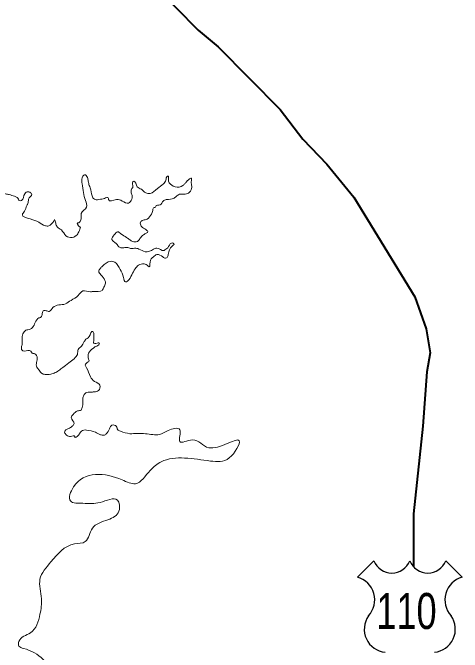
# Model space of a CAD drawing. Extents: x 553962 to 842807, y 8883888 to 9032388.
# Drawn here: x 579563 to 583934, y 8979171 to 8985392 of the extents above; entities that cross this region are included whole.
import ezdxf
from ezdxf.enums import TextEntityAlignment as Align

# ---------------------------------------------------------------- set-up
doc = ezdxf.new("R2010")
doc.units = 0
doc.header["$LTSCALE"] = 200
for name, color, linetype, lineweight in [('12', 7, 'Continuous', 25), ('25', 7, 'Continuous', 13), ('48', 7, 'Continuous', 25)]:
    doc.layers.add(name, color=color, linetype=linetype, lineweight=lineweight)

msp = doc.modelspace()

# ---------------------------------------------------------------- linework, layer by layer
at = {"layer": '12', "lineweight": 40}
msp.add_lwpolyline([(577759.9, 8988875.8), (577832.5, 8988674.7), (577901.5, 8988571.1), (578184.7, 8988310.3), (578513.4, 8987946.2), (578671.2, 8987814.3), (579419.2, 8987100.9), (579808.1, 8986794.1), (580283, 8986357.3), (580496.3, 8986108), (581364.8, 8985224.5), (581561.3, 8985062.5), (582162.5, 8984452.7), (582384.7, 8984161.9), (582616.4, 8983918.8), (582880.2, 8983596.7), (583472.4, 8982628.4), (583582.5, 8982317.7), (583621.7, 8982083.2), (583591.6, 8981897.8), (583552.5, 8981370), (583461.7, 8980518.1), (583461.7, 8980001.2)], dxfattribs=at)
at = {"layer": '25'}
for points in [[(579970.3, 8983381.7), (579928.3, 8983326.2), (579913.3, 8983318.6), (579880.6, 8983319.8), (579816, 8983353.5), (579732.6, 8983386), (579656.6, 8983427.2), (579677.5, 8983461.2), (579700.7, 8983516.6), (579706.8, 8983528), (579715.1, 8983564.5), (579723.5, 8983590.9), (579747, 8983622.4), (579727.8, 8983646.2), (579713.9, 8983650), (579679, 8983632.2), (579647.2, 8983565.5), (579623.3, 8983566.7), (579619.4, 8983578), (579581.3, 8983606.8), (579528.2, 8983623), (579513.1, 8983626.7), (579471.5, 8983636.7), (579433.4, 8983665.5), (579440.4, 8983701.9), (579442.4, 8983737.2), (579441.2, 8983739.7), (579447, 8983768.6), (579413, 8983867.8), (579391.3, 8983892.9), (579318.5, 8983971.9), (579294.2, 8984005.8), (579301.2, 8984042.2), (579315.8, 8984077.5), (579343, 8984115.3), (579355.3, 8984132.9), (579360.2, 8984143)], [(580290.3, 8983788.7), (580262.3, 8983816.3), (580235.2, 8983772.2), (580237.1, 8983729.5), (580249.6, 8983642.7), (580269.5, 8983564.8), (580280.4, 8983502), (580228.5, 8983437.7), (580228.9, 8983411.3), (580225.6, 8983377.4), (580205.8, 8983349.7), (580190.8, 8983343.3), (580198.6, 8983327), (580199.9, 8983323.2), (580212.7, 8983309.5), (580216.4, 8983308.2), (580211.9, 8983275.5), (580188.6, 8983232.7), (580142.4, 8983206.2), (580080.6, 8983222.3), (580035.8, 8983278.8), (579995.2, 8983308.8), (579980.9, 8983344), (579975.5, 8983366.6), (579970.3, 8983381.7)], [(581134, 8983136.2), (581123.8, 8983150.6), (581105.6, 8983150.6), (581070.3, 8983105.8), (581052.9, 8983091.9), (581034.2, 8983079.3), (580963.5, 8983103), (580932.2, 8983091.6), (580892.3, 8983071.3), (580850.8, 8983067.4), (580790.1, 8983093.7), (580748.6, 8983101.1), (580717.2, 8983098.5), (580683.1, 8983107.2), (580642.9, 8983105.8), (580622.8, 8983104.5), (580595, 8983115.7), (580573.2, 8983143.3), (580544, 8983165.8), (580526.1, 8983187.2), (580550.7, 8983231.2), (580582.9, 8983261.5), (580614.6, 8983241.5), (580670.4, 8983206.5), (580700.9, 8983182.7), (580728.8, 8983167.7), (580775.3, 8983167.8), (580800.1, 8983195.5), (580833.5, 8983232.1), (580860.9, 8983248.5), (580877.1, 8983263.7), (580868.1, 8983274.9), (580826.2, 8983303.7), (580804.4, 8983335.1), (580804.2, 8983354), (580830.3, 8983372.9), (580870.4, 8983385.6), (580911.2, 8983432.2), (580924.6, 8983468.7), (580931.7, 8983493.9), (580954.2, 8983506.5), (580954.2, 8983507.8), (580996.7, 8983524.3), (581025.1, 8983560.8), (581056.3, 8983574.7), (581131.6, 8983588.8), (581158.9, 8983611.5), (581195.2, 8983628), (581227.9, 8983628), (581273, 8983638.2), (581301.3, 8983683.6), (581303.5, 8983703.7), (581299.1, 8983749), (581299.9, 8983784.2), (581260.8, 8983756), (581236.5, 8983729.9), (581217.9, 8983712.2), (581141.4, 8983698.2), (581085.5, 8983738.3), (581076.3, 8983772.2), (581072.1, 8983803.6), (581068.3, 8983802.3), (581051.3, 8983763.3), (581027.9, 8983726.8), (580969.4, 8983681.3), (580898.4, 8983634.6), (580856.8, 8983640.8), (580813.6, 8983674.6), (580774.3, 8983699.6), (580739.6, 8983752.3), (580732.1, 8983748.5), (580731.6, 8983699.5), (580718.1, 8983675.6), (580716, 8983641.6), (580725.3, 8983605.2), (580720.6, 8983578.8), (580689.7, 8983539.7), (580627.8, 8983560.9), (580572.3, 8983574.6), (580493.2, 8983574.3), (580490.4, 8983591.9), (580477.8, 8983595.6), (580476.5, 8983595.6), (580454, 8983585.5), (580401.3, 8983576.6), (580373.7, 8983572.7), (580343.3, 8983592.7), (580322.1, 8983669.4), (580307.7, 8983710.8), (580297.1, 8983754.8), (580290.3, 8983788.7)], [(579888.2, 8982493.8), (579915.9, 8982486.3), (579954.3, 8982525.4), (580074.6, 8982559.7), (580129.7, 8982594), (580199.2, 8982640.5), (580243.8, 8982685.9), (580319.4, 8982677.4), (580352, 8982681.2), (580431.1, 8982691.5), (580449.5, 8982723), (580464.1, 8982760.8), (580459.9, 8982787.2), (580418.9, 8982842.4), (580399.6, 8982877.5), (580413.1, 8982902.7), (580435.4, 8982927.9), (580511.4, 8982973.4), (580556.8, 8982964.7), (580606.8, 8982894.5), (580640.6, 8982816.6), (580660, 8982773.9), (580678.8, 8982781.5), (580720.7, 8982842), (580753.8, 8982901.2), (580786, 8982936.5), (580839.9, 8982949.2), (580880.4, 8982928), (580889.3, 8982920.5), (580898.7, 8982967), (580930.7, 8983017.4), (580964.4, 8983038.9), (581023.8, 8983016.4), (581049.1, 8983003.9), (581064.1, 8983011.5), (581075, 8983041.7), (581112.8, 8983122.3), (581134, 8983136.2)], [(580701.6, 8981295.5), (580609.5, 8981320.4), (580584.1, 8981335.4), (580569.8, 8981369.3), (580528.2, 8981380.5), (580503.6, 8981343.9), (580472.8, 8981294.8), (580447.8, 8981282.2), (580415.1, 8981287.1), (580367, 8981310.8), (580278.7, 8981332), (580253.6, 8981331.9), (580216.2, 8981301.6), (580199, 8981278.9), (580166.5, 8981262.5), (580166.4, 8981268.8), (580124.9, 8981269.9), (580087, 8981282.4), (580067.8, 8981308.7), (580071.3, 8981326.3), (580116.2, 8981351.6), (580143.6, 8981371.8), (580160.9, 8981394.5), (580132.5, 8981452.2), (580152.1, 8981485), (580191.9, 8981517.8), (580212, 8981521.6), (580220.8, 8981522.9), (580239.2, 8981553.1), (580246.1, 8981602.2), (580243.1, 8981637.4), (580255.2, 8981671.3), (580273.8, 8981692.8), (580318.9, 8981701.7), (580355.3, 8981703.1), (580396.6, 8981715.8), (580411, 8981767.4), (580357.7, 8981806.2), (580318.1, 8981851.3), (580280.5, 8981938), (580268.8, 8981964.3), (580279.8, 8981983.2), (580304.7, 8982007.2), (580300.7, 8982023.5), (580301.2, 8982078.8), (580347, 8982129.3), (580379.4, 8982149.5), (580399.3, 8982162.1), (580405.4, 8982177.2), (580371.5, 8982174.6), (580352.6, 8982177.1), (580351, 8982206), (580351.8, 8982233.6), (580344.8, 8982286.4), (580341, 8982290.2), (580305.2, 8982242.3), (580266.7, 8982207), (580252, 8982179.3), (580221.1, 8982140.2), (580196.4, 8982107.5), (580194.3, 8982079.8), (580171, 8982037), (580122.5, 8981996.6), (580061.6, 8981949.9), (580021.7, 8981919.6), (579976.9, 8981890.6), (579931.8, 8981875.3), (579877.8, 8981872.7), (579841.2, 8981886.4), (579814.3, 8981922.8), (579804.1, 8981932.8), (579792.4, 8981955.4), (579798.1, 8982001.9), (579794.8, 8982057.2), (579778.2, 8982074.8), (579751.8, 8982079.7), (579738.9, 8982098.6), (579674.8, 8982100.9), (579653.3, 8982109.6), (579649, 8982146.1), (579653.8, 8982162.4), (579654.3, 8982216.5), (579689.6, 8982303.3), (579732.2, 8982313.5), (579754.6, 8982328.7), (579781.6, 8982379.1), (579817.5, 8982423.2), (579832.5, 8982428.2), (579848.5, 8982453.4), (579859.3, 8982492.4), (579888.2, 8982493.8)], [(581113.2, 8977420.6), (581052, 8977586.8), (581044.4, 8977701), (581112.9, 8977822.7), (581219.3, 8977944.5), (581226.9, 8977959.7), (581325.8, 8977997.7), (581150.9, 8978172.7), (581059.6, 8978180.3), (580846.7, 8978073.8), (580823.9, 8977997.7), (580687, 8978020.5), (580474.1, 8978324.9), (580542.6, 8978644.5), (580633.8, 8978751), (580808.7, 8978933.6), (580808.7, 8978941.2), (580763.1, 8978956.4), (580603.4, 8978888), (580382.9, 8978773.8), (580109.1, 8978811.9), (579858.2, 8979101), (579668.1, 8979207.5), (579622.5, 8979230.4), (579622.5, 8979276), (579736.5, 8979359.7), (579827.8, 8979539.3), (579843, 8979691.5), (579827.8, 8979881.7), (579934.2, 8980049.1), (580162.3, 8980224.1), (580268.8, 8980246.9), (580337.2, 8980376.3), (580489.3, 8980460), (580595.8, 8980543.7), (580580.6, 8980650.2), (580413.3, 8980627.4), (580246, 8980619.8), (580124.3, 8980642.6), (580154.7, 8980779.6), (580626.2, 8980848), (580755.5, 8980810), (580899.9, 8980939.3), (581006.4, 8981023), (581485.5, 8981030.6), (581667.9, 8981061.1), (581765.3, 8981228.5), (581468.7, 8981160), (581309, 8981236.1), (581187.4, 8981220.9), (581187.4, 8981335), (581073.3, 8981327.4), (580989.7, 8981289.3), (580852.8, 8981297), (580701.6, 8981295.5)]]:
    msp.add_spline(points, degree=3, dxfattribs=at)
at = {"layer": '48'}
for p, q in [((582914.9, 8979901.3), (583074.8, 8980061.2)), ((583774.1, 8980061.2), (583934.1, 8979901.3))]:
    msp.add_line(p, q, dxfattribs=at)
for centre, radius, start, end in [((583249.6, 8980128.1), 187.2, 200.95927, 339.04073), ((583599.3, 8980128.1), 187.2, 200.95927, 339.04073), ((582852.8, 8979679.4), 230.3, 317.5721, 74.36886), ((583996.1, 8979679.4), 230.3, 105.62774, 222.4279), ((583206.3, 8979394.3), 224.7, 144.73733, 264.65778), ((583642.6, 8979394.3), 224.7, 275.34222, 35.26267)]:
    msp.add_arc(centre, radius, start, end, dxfattribs=at)

# ---------------------------------------------------------------- texts
at = {"layer": '48', "width": 0.75}
msp.add_text('110', height=350, dxfattribs=at).set_placement((583392.5, 8979396.6), align=Align.CENTER)

doc.saveas('drawing.dxf')
